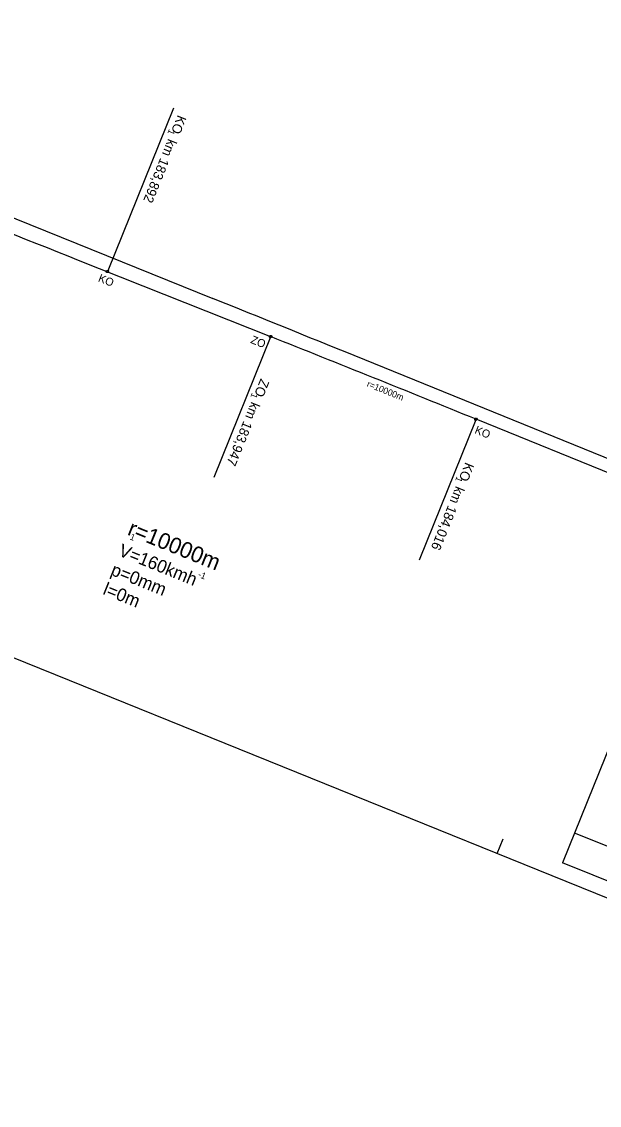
# Model space of a CAD drawing. Extents: x -467542 to -465211, y -1328177 to -1327037.
# Drawn here: x -465743.4 to -465562.9, y -1328177.4 to -1327838.8 of the extents above; entities that cross this region are included whole.
import ezdxf

# ---------------------------------------------------------------- set-up
doc = ezdxf.new("R2010")
doc.units = 0
for name, color, linetype in [('Level 1', 7, 'Continuous'), ('Level 10', 7, 'Continuous'), ('Level 11', 7, 'Continuous'), ('Level 61', 7, 'Continuous')]:
    doc.layers.add(name, color=color, linetype=linetype)

msp = doc.modelspace()

# ---------------------------------------------------------------- linework, layer by layer
at = {"layer": 'Level 1'}
for p, q in [((-465750.21, -1327898.43), (-465683.62, -1327925.29)), ((-465725.72, -1327913.31), (-465665.62, -1327937.22)), ((-465716.62, -1327916.85), (-465716.62, -1327916.85)), ((-465665.62, -1327937.22), (-465665.62, -1327937.22)), ((-465551.6, -1327978.83), (-465639.53, -1327943.13)), ((-465601.42, -1327963.03), (-465601.42, -1327963.03)), ((-465553.15, -1327982.63), (-465601.42, -1327963.03)), ((-465550.46, -1328042.25), (-465574.44, -1328101.59)), ((-465459.43, -1328137.27), (-465570.69, -1328092.32)), ((-465402.91, -1328170.89), (-465574.44, -1328101.59))]:
    msp.add_line(p, q, dxfattribs=at)
for points in [[(-465716.77, -1327917.22), (-465717.02, -1327916.91), (-465716.87, -1327916.54), (-465716.47, -1327916.48), (-465716.23, -1327916.79), (-465716.37, -1327917.16), (-465716.77, -1327917.22)], [(-465665.47, -1327936.85), (-465665.23, -1327937.16), (-465665.38, -1327937.53), (-465665.77, -1327937.59), (-465666.02, -1327937.28), (-465665.87, -1327936.91), (-465665.47, -1327936.85)], [(-465601.57, -1327963.4), (-465601.81, -1327963.08), (-465601.66, -1327962.72), (-465601.27, -1327962.66), (-465601.02, -1327962.98), (-465601.17, -1327963.34), (-465601.57, -1327963.4)]]:
    msp.add_lwpolyline(points, dxfattribs=at)
for centre, radius, start, end in [((-462028.55, -1318621.86), 10000, 247.980981, 248.301869), ((-473163.81, -1346473.79), 20000, 67.900644, 68.036914), ((-469363.2, -1337228.5), 10000, 67.902869, 68.299347)]:
    msp.add_arc(centre, radius, start, end, dxfattribs=at)
at = {"layer": 'Level 11'}
for p, q in [((-465695.91, -1327865.85), (-465716.46, -1327916.71)), ((-465665.5, -1327937.06), (-465683.36, -1327981.27)), ((-465601.5, -1327963.21), (-465619.22, -1328007.06))]:
    msp.add_line(p, q, dxfattribs=at)
at = {"layer": 'Level 61'}
for p, q in [((-465400.15, -1328177.4), (-466763.11, -1327626.73)), ((-465594.85, -1328098.73), (-465592.98, -1328094.1))]:
    msp.add_line(p, q, dxfattribs=at)

# ---------------------------------------------------------------- texts
at = {"layer": 'Level 10'}
msp.add_text('r=10000m', height=2, rotation=338, dxfattribs=at).set_placement((-465635.72, -1327952.75))
at = {"layer": 'Level 11'}
for s, height, rotation, p in [('KO  km 183,892', 3, 248, (-465694.6, -1327867.78)), ('1', 2, 248, (-465697.3, -1327872.26)), ('KO', 2.5, 338, (-465719.7, -1327919.88)), ('ZO', 2.5, 338, (-465672.09, -1327939.12)), ('ZO  km 183,947', 3, 248, (-465668.7, -1327950.16)), ('1', 2, 248, (-465671.4, -1327954.64)), ('KO', 2.5, 338, (-465602.04, -1327967.33)), ('KO  km 184,016', 3, 248, (-465604.7, -1327976.3)), ('1', 2, 248, (-465607.4, -1327980.78)), ('r=10000m', 5, 338, (-465710.66, -1327999.03)), ('1', 2, 338, (-465709.79, -1328000.52)), ('V=160kmh', 4, 338, (-465713.43, -1328005.53)), ('p=0mm', 4, 338, (-465715.87, -1328011.56)), ('-1', 2, 338, (-465688.49, -1328012.24)), ('l=0m', 4, 338, (-465718.3, -1328017.58))]:
    msp.add_text(s, height=height, rotation=rotation, dxfattribs=at).set_placement(p)

doc.saveas('drawing.dxf')
